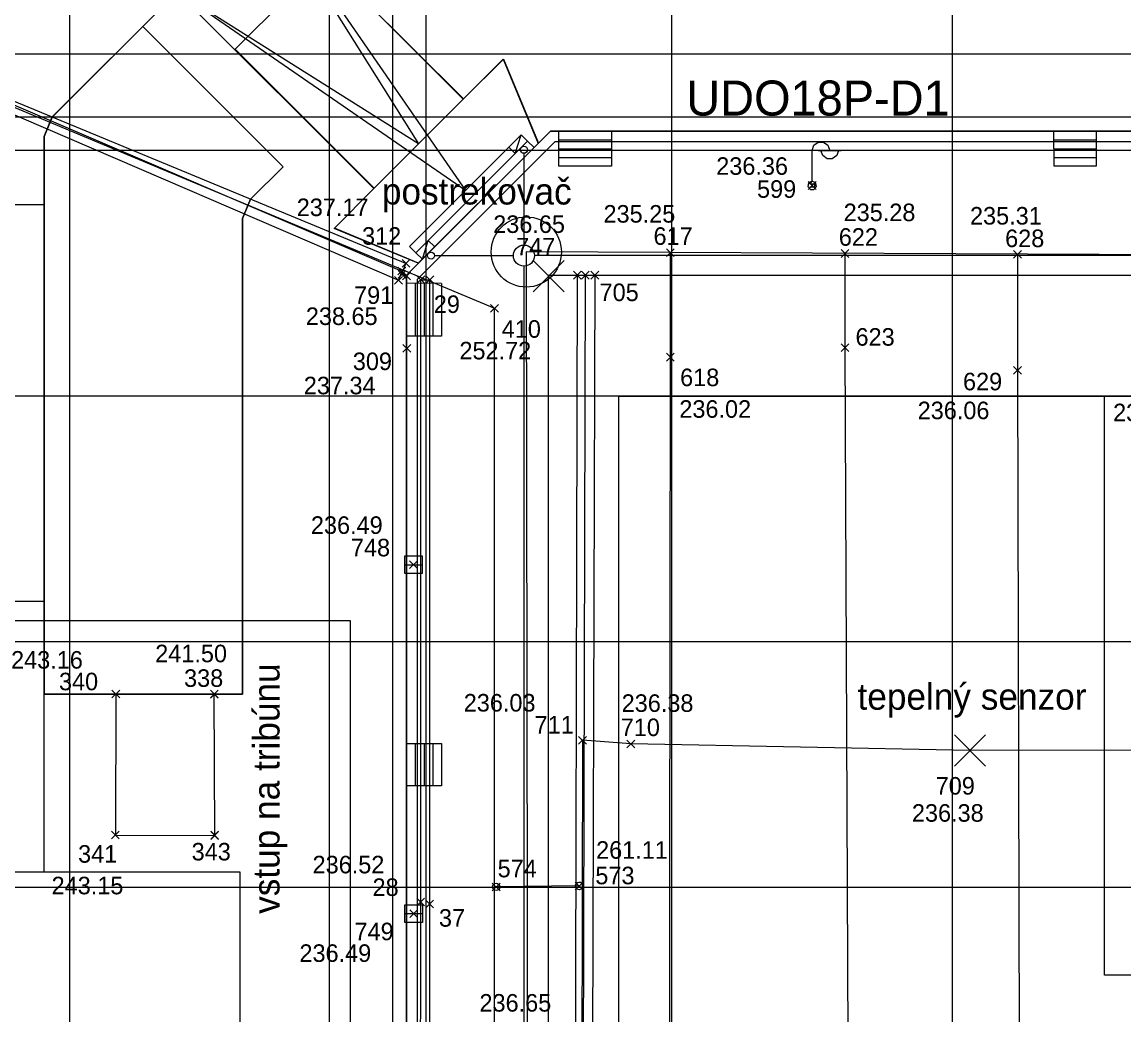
# Model space of a CAD drawing. Extents: x -264205 to -263659, y -1242401 to -1242060.
# Drawn here: x -263902.97 to -263871.58, y -1242129.52 to -1242101.22 of the extents above; entities that cross this region are included whole.
import ezdxf

# ---------------------------------------------------------------- set-up
doc = ezdxf.new("R2010")
doc.units = 0
for name, color, linetype in [('BOD_CISLO', 7, 'Continuous'), ('BOD_SYMBOL', 7, 'Continuous'), ('BOD_VYSKA', 7, 'Continuous'), ('KFA_SO_10-1_DRENAZNY_SYSTEM_IHRISKA', 7, 'Continuous'), ('KFA_SO_10-1_LIZATKA_POMOCNE', 7, 'Continuous'), ('KFA_SO_10-1_OBRUBNIKY_IHRISKO', 7, 'Continuous'), ('KFA_SO_10-1_OHREV', 7, 'Continuous'), ('KFA_SO_10-1_POSTREKOVACE', 7, 'Continuous'), ('KFA_SO_10-1_STRECHY', 7, 'Continuous'), ('KFA_SO_10-1_SVETELNE_VEZE', 7, 'Continuous'), ('KFA_SO_10-1_TEPELNE_SENZORY_A_TRASA', 7, 'Continuous'), ('KFA_SO_10-1_TRIBUNA_A_OBVOD', 7, 'Continuous'), ('KFA_SO_10-1_VPUST_STADION_POKLOP', 7, 'Continuous'), ('KFA_SO_10-1_VSTUPY_TRIBUNA_A', 7, 'Continuous'), ('KFA_SO_10-1_ZABRADLIE_STADION', 7, 'Continuous'), ('KFA_SO_40-2-II_DAZDOVA_KANALIZACIA', 7, 'Continuous'), ('OBRUBNIKY_KOMUNIKACIE_PROJEKT', 7, 'Continuous'), ('OSI_STAVBY_KFA', 7, 'Continuous'), ('POPIS', 7, 'Continuous'), ('SITUACIA_DSP_2D', 7, 'Continuous')]:
    doc.layers.add(name, color=color, linetype=linetype)

msp = doc.modelspace()

# ---------------------------------------------------------------- linework, layer by layer
at = {"layer": 'BOD_SYMBOL'}
for p, q in [((-263880.572, -1242105.99), (-263880.351, -1242105.769)), ((-263880.351, -1242105.99), (-263880.572, -1242105.769)), ((-263884.614, -1242107.903), (-263884.393, -1242107.681)), ((-263884.393, -1242107.903), (-263884.614, -1242107.681)), ((-263879.639, -1242107.927), (-263879.418, -1242107.705)), ((-263879.418, -1242107.927), (-263879.639, -1242107.705)), ((-263874.72, -1242107.95), (-263874.498, -1242107.728)), ((-263874.498, -1242107.95), (-263874.72, -1242107.728)), ((-263892.263, -1242108.427), (-263892.041, -1242108.207)), ((-263892.041, -1242108.427), (-263892.263, -1242108.207)), ((-263892.144, -1242108.211), (-263891.924, -1242107.99)), ((-263891.924, -1242108.211), (-263892.144, -1242107.99)), ((-263892.357, -1242108.691), (-263892.136, -1242108.47)), ((-263892.136, -1242108.691), (-263892.357, -1242108.47)), ((-263892.259, -1242108.519), (-263892.038, -1242108.298)), ((-263892.038, -1242108.519), (-263892.259, -1242108.298)), ((-263892.128, -1242108.569), (-263891.906, -1242108.349)), ((-263891.906, -1242108.569), (-263892.128, -1242108.349)), ((-263891.721, -1242108.676), (-263891.5, -1242108.454)), ((-263891.5, -1242108.676), (-263891.721, -1242108.454)), ((-263891.464, -1242108.676), (-263891.242, -1242108.454)), ((-263891.242, -1242108.676), (-263891.464, -1242108.454)), ((-263888.079, -1242108.573), (-263887.857, -1242108.353)), ((-263887.857, -1242108.573), (-263888.079, -1242108.353)), ((-263887.264, -1242108.545), (-263887.042, -1242108.323)), ((-263887.042, -1242108.545), (-263887.264, -1242108.323)), ((-263887.035, -1242108.545), (-263886.814, -1242108.323)), ((-263886.814, -1242108.545), (-263887.035, -1242108.323)), ((-263886.764, -1242108.545), (-263886.542, -1242108.323)), ((-263886.542, -1242108.545), (-263886.764, -1242108.323)), ((-263889.622, -1242109.488), (-263889.4, -1242109.268)), ((-263889.4, -1242109.488), (-263889.622, -1242109.268)), ((-263892.12, -1242110.632), (-263891.899, -1242110.41)), ((-263891.899, -1242110.632), (-263892.12, -1242110.41)), ((-263892.118, -1242110.632), (-263891.897, -1242110.41)), ((-263891.897, -1242110.632), (-263892.118, -1242110.41)), ((-263879.639, -1242110.609), (-263879.418, -1242110.387)), ((-263879.418, -1242110.609), (-263879.639, -1242110.387)), ((-263884.614, -1242110.882), (-263884.393, -1242110.66)), ((-263884.393, -1242110.882), (-263884.614, -1242110.66)), ((-263874.72, -1242111.258), (-263874.498, -1242111.038)), ((-263874.498, -1242111.258), (-263874.72, -1242111.038)), ((-263891.931, -1242116.796), (-263891.709, -1242116.576)), ((-263891.709, -1242116.796), (-263891.931, -1242116.576)), ((-263900.409, -1242120.482), (-263900.188, -1242120.262)), ((-263900.188, -1242120.482), (-263900.409, -1242120.262)), ((-263897.606, -1242120.482), (-263897.384, -1242120.262)), ((-263897.384, -1242120.482), (-263897.606, -1242120.262)), ((-263897.603, -1242120.484), (-263897.382, -1242120.262)), ((-263897.382, -1242120.484), (-263897.603, -1242120.262)), ((-263887.114, -1242121.799), (-263886.893, -1242121.579)), ((-263886.893, -1242121.799), (-263887.114, -1242121.579)), ((-263885.736, -1242121.903), (-263885.515, -1242121.681)), ((-263885.515, -1242121.903), (-263885.736, -1242121.681)), ((-263876.073, -1242122.09), (-263875.852, -1242121.869)), ((-263875.852, -1242122.09), (-263876.073, -1242121.869)), ((-263900.422, -1242124.501), (-263900.201, -1242124.279)), ((-263900.201, -1242124.501), (-263900.422, -1242124.279)), ((-263897.596, -1242124.511), (-263897.375, -1242124.289)), ((-263897.375, -1242124.511), (-263897.596, -1242124.289)), ((-263897.592, -1242124.502), (-263897.371, -1242124.282)), ((-263897.371, -1242124.502), (-263897.592, -1242124.282)), ((-263889.573, -1242125.978), (-263889.352, -1242125.757)), ((-263889.352, -1242125.978), (-263889.573, -1242125.757)), ((-263887.209, -1242125.948), (-263886.987, -1242125.727)), ((-263886.987, -1242125.948), (-263887.209, -1242125.727)), ((-263891.723, -1242126.404), (-263891.502, -1242126.184)), ((-263891.502, -1242126.404), (-263891.723, -1242126.184)), ((-263891.468, -1242126.463), (-263891.247, -1242126.242)), ((-263891.247, -1242126.463), (-263891.468, -1242126.242)), ((-263891.924, -1242126.738), (-263891.703, -1242126.516)), ((-263891.703, -1242126.738), (-263891.924, -1242126.516))]:
    msp.add_line(p, q, dxfattribs=at)
at = {"layer": 'KFA_SO_10-1_DRENAZNY_SYSTEM_IHRISKA'}
for p, q in [((-263884.503, -1242107.792), (-263884.503, -1242110.771)), ((-263879.529, -1242107.816), (-263879.529, -1242110.498)), ((-263874.609, -1242107.839), (-263874.609, -1242111.148)), ((-263879.529, -1242110.498), (-263879.285, -1242166.044)), ((-263874.609, -1242111.148), (-263874.484, -1242165.197))]:
    msp.add_line(p, q, dxfattribs=at)
msp.add_lwpolyline([(-263884.503, -1242110.771), (-263884.575, -1242164.194), (-263884.45, -1242219.174)], dxfattribs=at)
at = {"layer": 'KFA_SO_10-1_LIZATKA_POMOCNE'}
msp.add_line((-263887.098, -1242125.837), (-263889.463, -1242125.867), dxfattribs=at)
for centre, major_axis, ratio in [((-263889.463, -1242125.867), (0.0966, -0.041), 0.981396), ((-263887.098, -1242125.837), (-0.009, 0.109), 0.974572)]:
    msp.add_ellipse(centre, major_axis=major_axis, ratio=ratio, dxfattribs=at)
at = {"layer": 'KFA_SO_10-1_OBRUBNIKY_IHRISKO'}
msp.add_line((-263891.611, -1242108.565), (-263891.353, -1242108.565), dxfattribs=at)
for points in [[(-263891.626, -1242145.652), (-263891.632, -1242139.667), (-263891.612, -1242126.294), (-263891.611, -1242108.565)], [(-263891.367, -1242145.649), (-263891.352, -1242139.699), (-263891.357, -1242126.352), (-263891.353, -1242108.565)]]:
    msp.add_lwpolyline(points, dxfattribs=at)
at = {"layer": 'KFA_SO_10-1_OHREV'}
for points in [[(-263887.153, -1242108.434), (-263887.285, -1242164.665), (-263887.476, -1242220.33)], [(-263886.925, -1242108.434), (-263887.067, -1242164.606), (-263887.048, -1242220.33)], [(-263886.653, -1242108.434), (-263886.821, -1242164.626), (-263886.77, -1242220.33)]]:
    msp.add_lwpolyline(points, dxfattribs=at)
at = {"layer": 'KFA_SO_10-1_POSTREKOVACE'}
for p, q in [((-263888.41, -1242108.905), (-263887.526, -1242108.021)), ((-263887.526, -1242108.905), (-263888.41, -1242108.021))]:
    msp.add_line(p, q, dxfattribs=at)
at = {"layer": 'KFA_SO_10-1_STRECHY'}
msp.add_line((-263889.533, -1242219.411), (-263889.511, -1242109.378), dxfattribs=at)
msp.add_lwpolyline([(-263912.057, -1242100.011), (-263908.136, -1242101.59), (-263889.511, -1242109.378)], dxfattribs=at)
at = {"layer": 'KFA_SO_10-1_SVETELNE_VEZE'}
for p, q in [((-263880.286, -1242104.879), (-263879.636, -1242104.879)), ((-263880.461, -1242105.879), (-263880.461, -1242105.879))]:
    msp.add_line(p, q, dxfattribs=at)
for points in [[(-263880.524, -1242105.917), (-263880.386, -1242105.917), (-263880.386, -1242105.842), (-263880.524, -1242105.842), (-263880.461, -1242105.754), (-263880.561, -1242105.804), (-263880.586, -1242105.904), (-263880.511, -1242105.992), (-263880.411, -1242105.992), (-263880.336, -1242105.904), (-263880.361, -1242105.804), (-263880.461, -1242105.754), (-263880.461, -1242104.879), (-263880.411, -1242104.729), (-263880.286, -1242104.641), (-263880.136, -1242104.641), (-263880.011, -1242104.729), (-263879.961, -1242104.879)], [(-263879.711, -1242104.879), (-263879.761, -1242105.029), (-263879.886, -1242105.117), (-263880.036, -1242105.117), (-263880.161, -1242105.029), (-263880.211, -1242104.879)]]:
    msp.add_lwpolyline(points, dxfattribs=at)
at = {"layer": 'KFA_SO_10-1_TEPELNE_SENZORY_A_TRASA'}
for p, q in [((-263876.405, -1242122.421), (-263875.521, -1242121.537)), ((-263875.521, -1242122.421), (-263876.405, -1242121.537))]:
    msp.add_line(p, q, dxfattribs=at)
msp.add_lwpolyline([(-263827.921, -1242121.921), (-263875.963, -1242121.979), (-263885.626, -1242121.792), (-263887.003, -1242121.689), (-263887.052, -1242145.021), (-263887.18, -1242173.77), (-263887.177, -1242203.116), (-263886.892, -1242206.901)], dxfattribs=at)
at = {"layer": 'KFA_SO_10-1_TRIBUNA_A_OBVOD'}
for points in [[(-263892.034, -1242108.1), (-263908.657, -1242101.227), (-263908.879, -1242101.775), (-263908.891, -1242125.41)], [(-263892.039, -1242220.661), (-263892.154, -1242220.367), (-263892.023, -1242220.311), (-263892.026, -1242218.259), (-263892.022, -1242218.258), (-263892.014, -1242181.432), (-263893.611, -1242181.428), (-263893.622, -1242166.388), (-263895.226, -1242166.39), (-263895.226, -1242162.375), (-263893.627, -1242162.368), (-263893.627, -1242147.332), (-263892.023, -1242147.335), (-263892.008, -1242110.521), (-263892.009, -1242110.521), (-263892.017, -1242108.459), (-263892.149, -1242108.408), (-263892.034, -1242108.1)]]:
    msp.add_lwpolyline(points, dxfattribs=at)
at = {"layer": 'KFA_SO_10-1_VPUST_STADION_POKLOP'}
for p, q in [((-263891.82, -1242116.686), (-263891.82, -1242116.686)), ((-263891.813, -1242126.627), (-263891.813, -1242126.627))]:
    msp.add_line(p, q, dxfattribs=at)
for points in [[(-263892.07, -1242116.686), (-263892.07, -1242116.436), (-263891.57, -1242116.436), (-263891.57, -1242116.936), (-263892.07, -1242116.936), (-263892.07, -1242116.686), (-263891.57, -1242116.686)], [(-263892.063, -1242126.627), (-263892.063, -1242126.377), (-263891.563, -1242126.377), (-263891.563, -1242126.877), (-263892.063, -1242126.877), (-263892.063, -1242126.627), (-263891.563, -1242126.627)]]:
    msp.add_lwpolyline(points, dxfattribs=at)
at = {"layer": 'KFA_SO_10-1_VSTUPY_TRIBUNA_A'}
msp.add_line((-263897.481, -1242124.392), (-263897.495, -1242120.372), dxfattribs=at)
msp.add_lwpolyline([(-263897.495, -1242120.372), (-263897.492, -1242120.373), (-263900.298, -1242120.372), (-263900.312, -1242124.39), (-263897.486, -1242124.4), (-263897.481, -1242124.392)], dxfattribs=at)
at = {"layer": 'KFA_SO_10-1_ZABRADLIE_STADION'}
for p, q in [((-263907.321, -1242101.821), (-263892.152, -1242108.317)), ((-263907.419, -1242102.049), (-263892.247, -1242108.58)), ((-263892.152, -1242108.317), (-263892.247, -1242108.58))]:
    msp.add_line(p, q, dxfattribs=at)
at = {"layer": 'KFA_SO_40-2-II_DAZDOVA_KANALIZACIA'}
msp.add_lwpolyline([(-263814.907, -1242107.856), (-263851.887, -1242107.945), (-263888.606, -1242107.773), (-263888.523, -1242164.395), (-263888.701, -1242220.786)], dxfattribs=at)
msp.add_circle((-263888.606, -1242107.773), 1, dxfattribs=at)
at = {"layer": 'OBRUBNIKY_KOMUNIKACIE_PROJEKT'}
for p, q in [((-263896.003, -1242097.814), (-263890.399, -1242103.418)), ((-263895.995, -1242097.81), (-263891.672, -1242104.691)), ((-263902.112, -1242103.927), (-263898.54, -1242100.355)), ((-263892.944, -1242105.964), (-263898.552, -1242100.364)), ((-263891.672, -1242104.691), (-263898.533, -1242100.366)), ((-263892.944, -1242105.964), (-263890.399, -1242103.418)), ((-263902.343, -1242104.482), (-263902.112, -1242103.927)), ((-263902.343, -1242125.432), (-263902.343, -1242104.482)), ((-263909.043, -1242125.432), (-263902.343, -1242125.432))]:
    msp.add_line(p, q, dxfattribs=at)
at = {"layer": 'OSI_STAVBY_KFA'}
for p, q in [((-263901.618, -1242083.237), (-263901.618, -1242246.707)), ((-263894.218, -1242083.237), (-263894.218, -1242246.707)), ((-263892.418, -1242083.237), (-263892.418, -1242246.707)), ((-263891.468, -1242083.237), (-263891.468, -1242246.707)), ((-263884.468, -1242083.237), (-263884.468, -1242246.707)), ((-263876.468, -1242083.237), (-263876.468, -1242246.707)), ((-263792.653, -1242102.132), (-263911.523, -1242102.132)), ((-263792.653, -1242103.932), (-263911.523, -1242103.932)), ((-263792.653, -1242104.882), (-263911.523, -1242104.882)), ((-263792.653, -1242111.882), (-263911.523, -1242111.882)), ((-263792.653, -1242118.882), (-263917.453, -1242118.882)), ((-263792.653, -1242125.882), (-263909.343, -1242125.882))]:
    msp.add_line(p, q, dxfattribs=at)
at = {"layer": 'SITUACIA_DSP_2D'}
for p, q in [((-263896.003, -1242097.814), (-263890.399, -1242103.418)), ((-263895.995, -1242097.81), (-263890.341, -1242106.025)), ((-263896.896, -1242101.999), (-263894.351, -1242099.454)), ((-263894.351, -1242099.454), (-263890.391, -1242103.413)), ((-263902.112, -1242103.927), (-263898.54, -1242100.355)), ((-263892.944, -1242105.964), (-263898.552, -1242100.364)), ((-263890.341, -1242106.025), (-263898.533, -1242100.366)), ((-263899.53, -1242101.345), (-263902.113, -1242103.928)), ((-263902.113, -1242103.928), (-263899.53, -1242101.345)), ((-263895.529, -1242105.347), (-263899.53, -1242101.345)), ((-263899.53, -1242101.345), (-263895.529, -1242105.347)), ((-263892.937, -1242105.959), (-263896.896, -1242101.999)), ((-263890.399, -1242103.418), (-263889.262, -1242102.282)), ((-263890.391, -1242103.413), (-263889.254, -1242102.277)), ((-263889.262, -1242102.282), (-263888.268, -1242104.681)), ((-263889.254, -1242102.277), (-263888.26, -1242104.677)), ((-263902.343, -1242104.482), (-263902.112, -1242103.927)), ((-263902.113, -1242103.928), (-263902.343, -1242104.482)), ((-263902.343, -1242104.482), (-263902.113, -1242103.928)), ((-263902.343, -1242104.482), (-263902.343, -1242120.37)), ((-263902.343, -1242120.37), (-263902.343, -1242104.482)), ((-263902.343, -1242125.432), (-263902.343, -1242104.482)), ((-263887.916, -1242104.332), (-263892.018, -1242108.434)), ((-263891.932, -1242107.613), (-263888.75, -1242104.431)), ((-263888.75, -1242104.431), (-263889.103, -1242104.785)), ((-263888.921, -1242104.967), (-263888.75, -1242104.431)), ((-263888.918, -1242104.964), (-263888.75, -1242104.431)), ((-263888.566, -1242104.615), (-263888.75, -1242104.431)), ((-263888.26, -1242104.677), (-263887.916, -1242104.332)), ((-263887.916, -1242104.332), (-263816.02, -1242104.332)), ((-263816.02, -1242104.332), (-263887.916, -1242104.332)), ((-263887.677, -1242105.332), (-263887.678, -1242104.353)), ((-263886.179, -1242104.332), (-263886.179, -1242105.332)), ((-263873.567, -1242105.332), (-263873.571, -1242104.345)), ((-263872.369, -1242104.332), (-263872.369, -1242105.332)), ((-263891.749, -1242107.795), (-263888.567, -1242104.614)), ((-263887.792, -1242104.632), (-263891.718, -1242108.558)), ((-263888.268, -1242104.681), (-263891.681, -1242108.095)), ((-263888.383, -1242104.797), (-263891.565, -1242107.979)), ((-263888.919, -1242104.969), (-263889.103, -1242104.785)), ((-263889.103, -1242104.785), (-263888.921, -1242104.967)), ((-263888.383, -1242104.797), (-263888.567, -1242104.614)), ((-263816.144, -1242104.632), (-263887.792, -1242104.632)), ((-263887.677, -1242104.582), (-263886.179, -1242104.582)), ((-263887.677, -1242104.832), (-263886.179, -1242104.832)), ((-263873.567, -1242104.582), (-263872.369, -1242104.582)), ((-263873.567, -1242104.832), (-263872.369, -1242104.832)), ((-263888.921, -1242104.967), (-263888.918, -1242104.964)), ((-263888.673, -1242104.962), (-263888.673, -1242107.577)), ((-263887.677, -1242105.082), (-263886.179, -1242105.082)), ((-263873.567, -1242105.082), (-263872.369, -1242105.082)), ((-263896.465, -1242106.268), (-263895.529, -1242105.347)), ((-263895.529, -1242105.347), (-263896.465, -1242106.268)), ((-263886.179, -1242105.332), (-263887.677, -1242105.332)), ((-263872.369, -1242105.332), (-263873.567, -1242105.332)), ((-263894.08, -1242107.101), (-263892.944, -1242105.964)), ((-263894.073, -1242107.096), (-263892.937, -1242105.959)), ((-263896.693, -1242106.822), (-263896.465, -1242106.268)), ((-263896.465, -1242106.268), (-263896.693, -1242106.822)), ((-263902.343, -1242106.432), (-263903.343, -1242106.432)), ((-263896.693, -1242120.37), (-263896.693, -1242106.822)), ((-263896.693, -1242106.822), (-263896.693, -1242120.37)), ((-263891.681, -1242108.095), (-263894.08, -1242107.101)), ((-263891.673, -1242108.09), (-263894.073, -1242107.096)), ((-263891.748, -1242107.797), (-263891.932, -1242107.613)), ((-263891.396, -1242107.442), (-263891.749, -1242107.795)), ((-263891.565, -1242107.979), (-263891.396, -1242107.442)), ((-263891.565, -1242107.979), (-263891.396, -1242107.442)), ((-263891.212, -1242107.626), (-263891.396, -1242107.442)), ((-263891.565, -1242107.979), (-263891.749, -1242107.795)), ((-263891.749, -1242107.795), (-263891.565, -1242107.979)), ((-263891.517, -1242107.934), (-263891.673, -1242108.089)), ((-263891.218, -1242107.877), (-263888.973, -1242107.877)), ((-263852.268, -1242107.877), (-263888.373, -1242107.877)), ((-263892.018, -1242108.434), (-263891.673, -1242108.09)), ((-263888.673, -1242108.177), (-263888.673, -1242164.087)), ((-263892.018, -1242147.332), (-263892.018, -1242108.434)), ((-263892.018, -1242108.434), (-263892.018, -1242147.332)), ((-263891.718, -1242108.558), (-263891.718, -1242147.632)), ((-263887.968, -1242108.434), (-263815.968, -1242108.434)), ((-263887.968, -1242220.33), (-263887.968, -1242108.434)), ((-263891.018, -1242108.673), (-263892.012, -1242108.664)), ((-263891.768, -1242108.673), (-263891.768, -1242110.171)), ((-263891.518, -1242108.673), (-263891.518, -1242110.171)), ((-263891.268, -1242108.673), (-263891.268, -1242110.171)), ((-263891.018, -1242108.673), (-263891.018, -1242110.171)), ((-263891.018, -1242110.171), (-263891.997, -1242110.171)), ((-263885.968, -1242111.882), (-263817.968, -1242111.882)), ((-263885.968, -1242216.882), (-263885.968, -1242111.882)), ((-263872.128, -1242128.382), (-263872.128, -1242111.882)), ((-263872.128, -1242111.882), (-263831.808, -1242111.882)), ((-263902.343, -1242117.732), (-263903.343, -1242117.732)), ((-263893.618, -1242118.282), (-263916.093, -1242118.282)), ((-263893.618, -1242162.382), (-263893.618, -1242118.282)), ((-263902.343, -1242120.37), (-263896.693, -1242120.37)), ((-263896.693, -1242120.37), (-263902.343, -1242120.37)), ((-263892.018, -1242121.782), (-263891.018, -1242121.782)), ((-263891.768, -1242121.782), (-263891.768, -1242122.982)), ((-263891.518, -1242121.782), (-263891.518, -1242122.982)), ((-263891.268, -1242121.782), (-263891.268, -1242122.982)), ((-263891.018, -1242121.782), (-263891.018, -1242122.982)), ((-263891.018, -1242122.982), (-263892.018, -1242122.982)), ((-263909.118, -1242125.432), (-263896.768, -1242125.432)), ((-263909.043, -1242125.432), (-263902.343, -1242125.432)), ((-263896.768, -1242125.432), (-263896.768, -1242147.182)), ((-263831.808, -1242128.382), (-263872.128, -1242128.382))]:
    msp.add_line(p, q, dxfattribs=at)
for centre, radius in [((-263888.673, -1242104.862), 0.1), ((-263888.673, -1242107.877), 0.3), ((-263891.318, -1242107.877), 0.1)]:
    msp.add_circle(centre, radius, dxfattribs=at)

# ---------------------------------------------------------------- texts
at = {"layer": 'BOD_CISLO'}
for s, p in [('599', (-263882.031, -1242106.23)), ('312', (-263893.284, -1242107.567)), ('617', (-263884.98, -1242107.57)), ('622', (-263879.702, -1242107.596)), ('628', (-263874.963, -1242107.635)), ('747', (-263888.894, -1242107.872)), ('791', (-263893.511, -1242109.253)), ('705', (-263886.517, -1242109.173)), ('29', (-263891.24, -1242109.511)), ('410', (-263889.305, -1242110.218)), ('623', (-263879.225, -1242110.444)), ('309', (-263893.547, -1242111.139)), ('618', (-263884.223, -1242111.597)), ('629', (-263876.163, -1242111.715)), ('748', (-263893.601, -1242116.447)), ('340', (-263901.919, -1242120.263)), ('338', (-263898.355, -1242120.166)), ('711', (-263888.368, -1242121.495)), ('710', (-263885.914, -1242121.569)), ('709', (-263876.941, -1242123.236)), ('343', (-263898.139, -1242125.112)), ('341', (-263901.374, -1242125.176)), ('574', (-263889.422, -1242125.593)), ('573', (-263886.638, -1242125.791)), ('28', (-263892.985, -1242126.124)), ('37', (-263891.094, -1242127)), ('749', (-263893.499, -1242127.386))]:
    msp.add_text(s, height=0.5, dxfattribs=at).set_placement(p)
at = {"layer": 'BOD_VYSKA'}
for s, p in [('236.36', (-263883.194, -1242105.575)), ('237.17', (-263895.145, -1242106.751)), ('235.28', (-263879.564, -1242106.895)), ('235.25', (-263886.405, -1242106.937)), ('235.31', (-263875.964, -1242106.992)), ('236.65', (-263889.548, -1242107.231)), ('238.65', (-263894.886, -1242109.854)), ('252.72', (-263890.51, -1242110.834)), ('237.34', (-263894.944, -1242111.829)), ('236.02', (-263884.245, -1242112.498)), ('236.06', (-263877.455, -1242112.538)), ('236.11', (-263871.887, -1242112.597)), ('236.49', (-263894.741, -1242115.807)), ('241.50', (-263899.177, -1242119.465)), ('243.16', (-263903.284, -1242119.646)), ('236.03', (-263890.387, -1242120.869)), ('236.38', (-263885.888, -1242120.879)), ('236.38', (-263877.619, -1242124.009)), ('261.11', (-263886.616, -1242125.064)), ('236.52', (-263894.694, -1242125.48)), ('243.15', (-263902.129, -1242126.077)), ('236.49', (-263895.068, -1242128.003)), ('236.65', (-263889.939, -1242129.42))]:
    msp.add_text(s, height=0.5, dxfattribs=at).set_placement(p)
at = {"layer": 'KFA_SO_10-1_SVETELNE_VEZE'}
msp.add_text('UDO18P-D1', height=1, dxfattribs=at).set_placement((-263884.048, -1242103.888))
at = {"layer": 'POPIS'}
for s, p in [('postrekovač', (-263892.72, -1242106.421)), ('tepelný senzor', (-263879.169, -1242120.817))]:
    msp.add_text(s, height=0.75, dxfattribs=at).set_placement(p)
msp.add_text('vstup na tribúnu', height=0.75, rotation=90, dxfattribs=at).set_placement((-263895.636, -1242126.634))

doc.saveas('drawing.dxf')
